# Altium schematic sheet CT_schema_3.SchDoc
size 187 x 169 mm
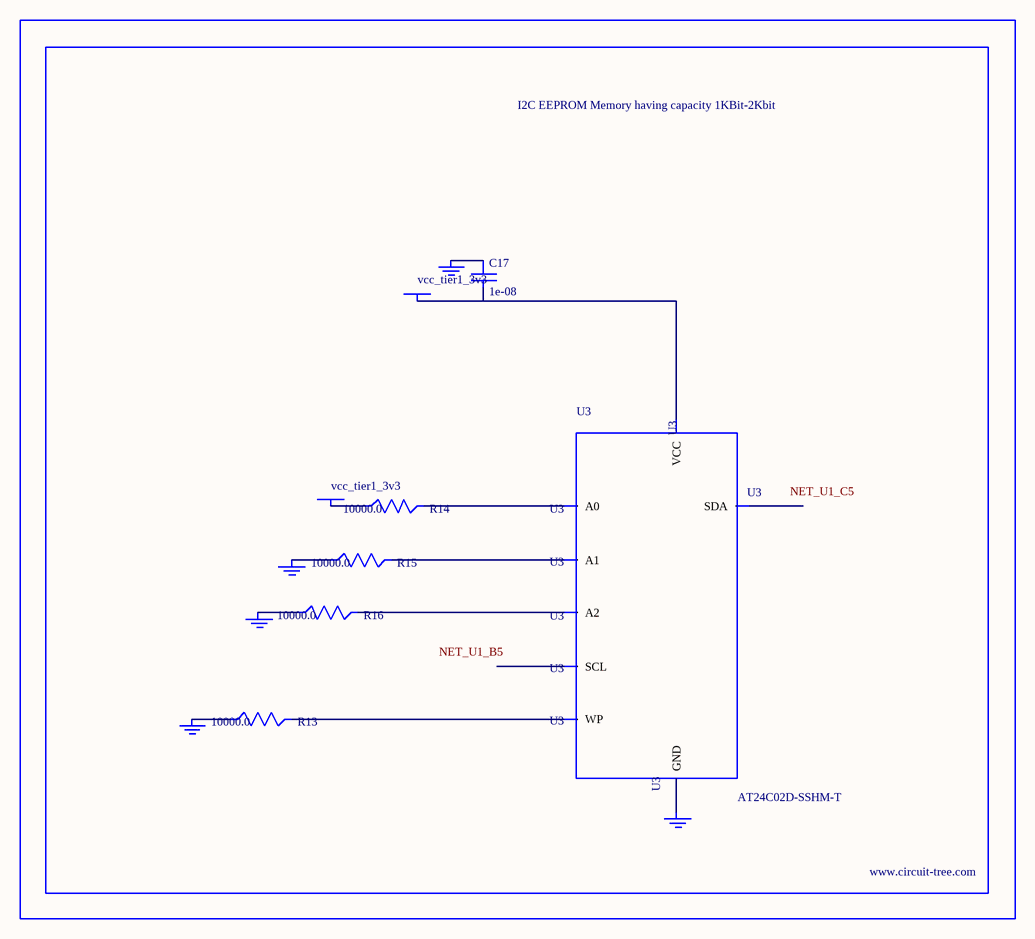
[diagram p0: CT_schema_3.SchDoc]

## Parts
BORDER2  (no value)
C17  1e-08  [C0402]
GND_INSTANCE_2_0  (no value)
GND_INSTANCE_2_1  (no value)
GND_INSTANCE_2_2  (no value)
GND_INSTANCE_2_3  (no value)
GND_INSTANCE_2_4  (no value)
POWER_INSTANCE_2_0  vcc_tier1_3v3
POWER_INSTANCE_2_1  vcc_tier1_3v3
R13  10000.0  [R0603]
R14  10000.0  [R0603]
R15  10000.0  [R0603]
R16  10000.0  [R0603]
U3  AT24C02D-SSHM-T  [AT24C02D]

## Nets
NetC17_1: C17.1 GND_INSTANCE_2_3.0(GND)
NetC17_2: C17.2 POWER_INSTANCE_2_1.0(PWR) U3.8(VCC)
NetGND_INSTANCE_2_0_0: GND_INSTANCE_2_0.0(GND) R15.1
NetGND_INSTANCE_2_1_0: GND_INSTANCE_2_1.0(GND) R16.1
NetGND_INSTANCE_2_2_0: GND_INSTANCE_2_2.0(GND) R13.1
NetGND_INSTANCE_2_4_0: GND_INSTANCE_2_4.0(GND) U3.4(GND)
NetPOWER_INSTANCE_2_0_0: POWER_INSTANCE_2_0.0(PWR) R14.1
NetR13_2: R13.2 U3.7(WP)
NetR14_2: R14.2 U3.1(A0)
NetR15_2: R15.2 U3.2(A1)
NetR16_2: R16.2 U3.3(A2)

Not connected (* = marked no-connect by the designer): U3 5(SDA) 6(SCL)

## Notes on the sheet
- Labels drawn without touching a wire or pin: NET_U1_B5, NET_U1_C5

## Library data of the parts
BORDER2 = BORDER_PAGE2
C17 = C0402C103K3RAC
GND_INSTANCE_2_0-GND_INSTANCE_2_4 = GND
POWER_INSTANCE_2_0 POWER_INSTANCE_2_1 = PWR
R13-R16 = RC0603JR-0710KL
